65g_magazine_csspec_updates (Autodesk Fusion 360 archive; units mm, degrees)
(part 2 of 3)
sketch "follower top profile" plane through (0, 0, 0) normal (0, 1, 0) x axis (1, 0, 0)
  line L1 (10.49, 30.115) -> (10.49, 3.75)
  line L2 (7.3787, 34.5802) -> (7.3787, 52.364)
  line L3 (-7.3787, 34.7452) -> (-7.3787, 52.2758)
  line L4 (-10.49, 30.5753) -> (-10.49, 3.75)
  line L5 (-7.49, 0.75) -> (0, 0.75)
  line L6 (7.49, 0.75) -> (0, 0.75)
  line L7 (-6.25, 20.5961) -> (6.25, 20.5961)
  line L8 (0, 4.25) -> (0, 55.9239)
  line L9 (0, 0) -> (0, 4.25)
  line L10 (-6.25, 12.5809) -> (-6.25, 36.1163)
  line L11 (6.25, 36.1163) -> (6.25, 12.5809)
  line L12 (0, 12.5809) -> (0, 36.1163)
  line L13 (-6.25, 12.5809) -> (6.25, 12.5809)
  line L14 (6.2185, 35.49) -> (-6.2185, 35.49)
  line L15 (-6.25, 13.5809) -> (6.25, 13.5809)
  line L16 (6.25, 34.49) -> (-6.25, 34.49)
  line L17 (-4.25, 12.5809) -> (-4.25, 36.1163)
  line L18 (4.25, 36.1163) -> (4.25, 12.5809)
  line L19 (-7.49, 2.55) -> (0, 2.55)
  line L20 (-8.69, 29.5833) -> (-8.69, 3.75)
  line L21 (-5.5787, 33.643) -> (-5.5787, 52.212)
  line L22 (-3.8484, 54.1526) -> (0, 54.147)
  line L23 (3.9642, 54.1413) -> (0, 54.147)
  line L24 (5.5787, 33.643) -> (5.5787, 52.2656)
  line L25 (8.69, 29.2715) -> (8.69, 3.75)
  line L26 (7.49, 2.55) -> (0, 2.55)
  line L27 (-8.69, 8.75) -> (-10.49, 8.75)
  line L28 (10.49, 8.75) -> (8.69, 8.75)
  line L29 (-7.3787, 46.15) -> (-5.5787, 46.15)
  line L30 (7.3787, 46.15) -> (5.5787, 46.15)
  line L31 (11, 0) -> (0, 0)
  line L32 (-11, 0) -> (0, 0)
  line L33 (-1.5, 26.4663) -> (1.5, 26.4663)
  line L34 (-1.5, 20.5863) -> (-1.5, 26.4663)
  line L35 (1.5, 20.5863) -> (-1.5, 20.5863)
  line L36 (1.5, 26.4663) -> (1.5, 20.5863)
  line L37 (0, 20.5863) -> (0, 26.4663)
  line L38 (-1.5, 23.9663) -> (1.5, 23.9663)
  line L39 (-1.5, 18.0863) -> (-1.5, 20.5863)
  line L40 (1.5, 18.0863) -> (-1.5, 18.0863)
  line L41 (1.5, 20.5863) -> (1.5, 18.0863)
  line L42 (-2.4679, 4.7609) -> (1.7552, 4.7609)
  line L43 (0, 1.2302) -> (0, 0)
  line L44 (-8.69, 6.25) -> (8.69, 6.25)
  line L45 (-1.85, 3.3229) -> (1.85, 3.3229)
  line L46 (-1.85, 4.9829) -> (-1.85, 3.3229)
  line L47 (-0.6223, 4.8) -> (-0.6223, 4.6416)
  line L48 (1.85, 4.9829) -> (1.85, 3.3229)
  line L49 (5.5787, 48.15) -> (-5.5787, 48.15)
  line L50 (-3.9765, 37.6163) -> (3.9765, 37.6163)
  line L51 (7.3787, 33.643) -> (-7.3787, 33.643)
  line L52 (3.7962, 55.9465) -> (-3.9836, 55.9465)
  line L53 (9.7698, 31.6519) -> (8.0989, 33.0433)
  line L54 (-9.5582, 32.2662) -> (-8.3105, 33.0543)
  line L55 (-7.7582, 31.2742) -> (-6.5105, 32.0624)
  line L56 (7.9698, 30.8084) -> (6.2989, 32.1998)
  line L57 (5.5787, 33.7367) -> (5.5787, 33.643)
  line L58 (-5.5787, 33.7532) -> (-5.5787, 33.643)
  arc A1 centre (3.7962, 52.364) radius 3.5825 clockwise from (3.7962, 55.9465) to (7.3787, 52.364)
  arc A2 centre (-3.6968, 52.2758) radius 3.6819 clockwise from (-7.3787, 52.2758) to (-3.9836, 55.9465)
  arc A3 centre (7.49, 3.75) radius 3 clockwise from (10.49, 3.75) to (7.49, 0.75)
  arc A4 centre (-7.49, 3.75) radius 3 clockwise from (-7.49, 0.75) to (-10.49, 3.75)
  arc A5 centre (0, 12.5809) radius 6.25 clockwise from (6.25, 12.5809) to (-6.25, 12.5809)
  arc A6 centre (0, 36.1163) radius 6.25 clockwise from (-6.25, 36.1163) to (6.25, 36.1163)
  arc A7 centre (0, 36.1163) radius 4.25 clockwise from (-4.25, 36.1163) to (4.25, 36.1163)
  arc A8 centre (0, 12.5809) radius 4.25 clockwise from (4.25, 12.5809) to (-4.25, 12.5809)
  arc A9 centre (-7.49, 3.75) radius 1.2 clockwise from (-7.49, 2.55) to (-8.69, 3.75)
  arc A10 centre (-3.6968, 52.2758) radius 1.883 clockwise from (-5.5787, 52.212) to (-3.8484, 54.1526)
  arc A11 centre (3.7962, 52.364) radius 1.7852 clockwise from (3.9642, 54.1413) to (5.5787, 52.2656)
  arc A12 centre (7.49, 3.75) radius 1.2 clockwise from (8.69, 3.75) to (7.49, 2.55)
  arc A13 centre (0, 12.5809) radius 7.82 clockwise from (4.5904, 6.25) to (1.85, 4.9829)
  arc A14 centre (0, 12.5809) radius 7.82 clockwise from (-1.85, 4.9829) to (-4.5904, 6.25)
  arc A15 centre (-6.69, 29.5833) radius 2 clockwise from (-8.69, 29.5833) to (-7.7582, 31.2742)
  arc A16 centre (-8.49, 30.5753) radius 2 clockwise from (-10.49, 30.5753) to (-9.5582, 32.2662)
  arc A17 centre (-7.5787, 33.7532) radius 2 clockwise from (-5.5787, 33.7532) to (-6.5105, 32.0624)
  arc A18 centre (-9.3787, 34.7452) radius 2 clockwise from (-7.3787, 34.7452) to (-8.3105, 33.0543)
  arc A19 centre (6.69, 29.2715) radius 2 clockwise from (7.9698, 30.8084) to (8.69, 29.2715)
  arc A20 centre (7.5787, 33.7367) radius 2 clockwise from (6.2989, 32.1998) to (5.5787, 33.7367)
  arc A21 centre (8.49, 30.115) radius 2 clockwise from (9.7698, 31.6519) to (10.49, 30.115)
  arc A22 centre (9.3787, 34.5802) radius 2 clockwise from (8.0989, 33.0433) to (7.3787, 34.5802)
  point P29 (0, 12.5809)
  point P30 (-6.2185, 35.49)
  point P31 (6.2185, 35.49)
  point P34 (-6.25, 34.49)
  point P35 (6.25, 34.49)
  point P58 (-10.49, 8.75)
  point P59 (-8.69, 8.75)
  point P60 (8.69, 8.75)
  point P61 (10.49, 8.75)
  point P62 (-5.5787, 46.15)
  point P63 (-7.3787, 46.15)
  point P64 (5.5787, 46.15)
  point P65 (7.3787, 46.15)
  point P74 (0, 26.4663)
  point P75 (0, 20.5863)
  point P76 (1.5, 23.9663)
  point P77 (-1.5, 23.9663)
  point P68 (0, 0)
  point P83 (0, 0)
  point P85 (8.69, 6.25)
  point P86 (-8.69, 6.25)
  point P87 (-4.5904, 6.25)
  point P88 (4.5904, 6.25)
  point P94 (1.85, 4.9829)
  point P96 (-5.5787, 48.15)
  point P97 (5.5787, 48.15)
  point P98 (3.9765, 37.6163)
  point P99 (-3.9765, 37.6163)
  point P54 (5.5787, 33.643)
  point P46 (-5.5787, 33.643)
  point P10 (-7.3787, 33.643)
  point P2 (10.49, 31.0522)
  point P3 (7.3787, 33.643)
  point P18 (6.25, 20.5961)
  point P19 (-6.25, 20.5961)
  point P22 (0, 0)
  point P72 (-1.5, 20.5863)
  point P73 (1.5, 20.5863)
  point P78 (-1.5, 18.0863)
  point P89 (1.85, 3.3229)
  point P90 (-1.85, 3.3229)
  point P91 (-1.85, 4.9829)
  point P28 (0, 36.1163)
  point P36 (0, 36.1163)
  point P71 (-1.5, 26.4663)
  point P84 (0, 1.2302)
  tangent A2 L3
  tangent L2 A1
  tangent L1 A3
  tangent L6 A3
  tangent L4 A4
  tangent L5 A4
  equal A3 A4
  vertical L8
  tangent L10 A5
  tangent A5 L11
  parallel L10 L11
  tangent L11 A6
  tangent L10 A6
  coincident L8 P29
  parallel L8 L12
  coincident A6 P30
  coincident A6 P31
  perpendicular L10 L14
  coincident L10 P34
  coincident L11 P35
  coincident L4 P58
  coincident L20 P59
  perpendicular L20 L27
  coincident L25 P60
  coincident L1 P61
  perpendicular L1 L28
  coincident L21 P62
  coincident L3 P63
  perpendicular L3 L29
  coincident L24 P64
  coincident L2 P65
  perpendicular L2 L30
  horizontal L33
  vertical L34
  horizontal L35
  vertical L36
  midpoint L33 P74
  midpoint L35 P75
  collinear L12 L37
  coincident L36 P76
  coincident L34 P77
  perpendicular L34 L38
  horizontal L6
  horizontal L5
  perpendicular L35 L39
  vertical L41
  horizontal L40
  horizontal L42
  tangent L42 A14
  coincident P68 P83
  perpendicular L32 L43
  collinear L9 L43
  coincident L25 P85
  coincident L20 P86
  perpendicular L20 L44
  concentric A5 A14
  coincident L44 P87
  coincident L44 P88
  horizontal L45
  perpendicular L42 L46
  perpendicular L42 L47
  coincident P94 A14
  perpendicular L45 L48
  concentric A13 A14
  coincident L21 P96
  coincident L24 P97
  perpendicular L24 L49
  coincident A7 P98
  coincident A7 P99
  horizontal L50
  perpendicular L2 L51
  coincident P54 L51
  coincident P46 L51
  vertical L2
  tangent A1 L52
  concentric A4 A9
  concentric A2 A10
  concentric A1 A11
  concentric A3 A12
  tangent A12 L26
  tangent L25 A12
  tangent L19 A9
  tangent A9 L20
  perpendicular L51 L57
  perpendicular L51 L58
  tangent L20 A15
  tangent L55 A15
  tangent L4 A16
  tangent L54 A16
  equal A15 A16
  tangent L55 A17
  tangent L58 A17
  equal A15 A17
  coincident P10 L3
  coincident P10 L54
  tangent L3 A18
  tangent L54 A18
  tangent L25 A19
  tangent L56 A19
  tangent L56 A20
  tangent L57 A20
  equal A19 A20
  coincident P2 L1
  coincident P2 L53
  tangent L1 A21
  tangent L53 A21
  equal A19 A21
  coincident P3 L53
  coincident P3 L2
  tangent L53 A22
  tangent L2 A22
  dimension "d895" radius A3 = 3
  dimension "d938" distance P18 P19 = 12.5
  dimension "d943" distance P19 L8 = 6.25 (= "d938 / 2")
  dimension "d947" radius A5 = 6.25 (= "d938 / 2")
  dimension "d958" = 1
  dimension "d959" = 1
  dimension "d960" = -2
  dimension "d967" distance L5 L27 = 8
  dimension "d968" distance L6 L28 = 8 (= "d967")
  dimension "d1005" distance L5 P29 = 11.8309
  dimension "d1006" distance P22 P29 = 12.5809
  dimension "d1008" distance P72 P73 = 3
  dimension "d1010" distance L33 L38 = 2.5
  dimension "d1011" distance L5 L32 = 0.75
  dimension "d1012" distance P72 P78 = 2.5
  dimension "d1016" distance L35 L38 = 3.38
  dimension "d1018" distance L6 L44 = 5.5
  dimension "d1019" distance P89 P90 = 3.7
  dimension "d1020" distance L9 P90 = 1.85 (= "d1019 / 2")
  dimension "d1021" distance P90 P91 = 1.66
  dimension "d1022" distance L29 L49 = 2
  dimension "d1034" distance P28 L50 = 1.5
  dimension "d1099" distance P36 P71 = 9.65
  dimension "d1157" distance P2 L6 = 30.3022
  dimension "d1158" distance P3 L6 = 32.893
  dimension "d1159" distance L1 P84 = 10.49
  dimension "d1160" distance L4 L8 = 10.49 (= "d1159")
  dimension "d1161" distance L2 L3 = 14.7574
  dimension "d1162" distance L3 L8 = 7.3787 (= "d1161 / 2")
  dimension "d1165" radius A15 = 2
  dimension "d1166" radius A18 = 2
  dimension "d1167" radius A19 = 2
  dimension "d1168" radius A22 = 2
  dimension "d1169" distance L5 L52 = 55.1965
fillet "Fillet14" radius 1
sweep "Sweep2" sketch "follower top profile" TwistAngle 0 TaperAngle 0
extrude "Extrude1" new body sketch "follower top profile" profile of L6 A2 L5 L4 A1 L2 L3 L1 A3 A4 L7 L10 A5 L11 A6 L15 L16 L18 A8 L17 A7 L26 A12 L25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 against normal blind 4 bodies "definesSketchPlane"
sketch "bullet offsetter bump" plane through (0, 0, -0.75) normal (0, 0, 1) x axis (1, 0, 0)
  line L1 (-7.49, 0) -> (7.49, 0)
  line L2 (-7.49, -4) -> (-7.49, 0)
  line L3 (7.49, -4) -> (-7.49, -4)
  line L4 (7.49, 0) -> (7.49, -4)
  line L5 (-10.49, 0) -> (-7.49, 0)
  line L6 (-10.49, -4) -> (-10.49, 0)
  line L7 (-7.49, -4) -> (-10.49, -4)
  line L8 (-7.49, 0) -> (-7.49, -4)
  line L9 (-0.14, 0) -> (-10.49, 0)
  line L10 (-0.14, 4.5) -> (-0.14, 0)
  line L11 (-6.99, 4.5) -> (-0.14, 4.5)
  line L12 (-10.49, 0) -> (-10.49, 1)
  line L13 (-10.49, 1) -> (-6.99, 4.5)
  point P7 (-10.49, 0)
  point P10 (-10.49, 0)
  point P13 (-10.49, 0)
  point P12 (-10.49, 4.5)
  point P14 (-0.14, 4.5)
  point P15 (-0.14, 4.5)
  point P11 (-0.14, 0)
  point P16 (-6.99, 4.5)
  point P17 (-10.49, 1)
  coincident P7 P10
  perpendicular L6 L9
  perpendicular L1 L10
  coincident P7 P13
  horizontal L11
  vertical L12
  coincident P12 L11
  coincident P12 L12
  coincident P14 P15
  dimension "d900" distance P10 P11 = 10.35
  dimension "d903" distance P12 P16 = 3.5
  dimension "d904" distance P12 P17 = 3.5 (= "d903")
  dimension "d915" distance P11 P14 = 4.5
extrude "Extrude2" new body sketch "bullet offsetter bump" profile of L1 L5 L9 L10 L11 L12 L13 against normal blind 33.5
fillet "Fillet1" radius 3 2
fillet "Fillet6" radius 4
chamfer "Chamfer2" distance 4 distance 4
fillet "Fillet7" radius 2
extrude "Extrude4" new body sketch "follower top profile" profile of L10 L11 A6 L16 L18 L17 A7 L50 blind -7 from offset -2
work_plane "WorkPlane2" AlongDistance -12.79
sweep "Sweep1" sketch "follower top profile" TwistAngle 0 TaperAngle 0
sweep "Sweep3" sketch "follower top profile" TwistAngle 0 TaperAngle 0
sketch "Sketch3" plane through (0, -13.1437, -0.1123) normal (0, -1, -0.0085) x axis (-1, 0, 0)
  line L1 (7.3787, 52.2196) -> (7.3787, 46.0938)
  line L2 (-3.7962, 55.8903) -> (3.9836, 55.8903)
  line L3 (-7.3787, 46.0938) -> (-7.3787, 52.3078)
  line L4 (-5.5787, 46.0938) -> (-7.3787, 46.0938)
  line L5 (-5.5787, 48.0938) -> (-5.5787, 46.0938)
  line L6 (5.5787, 48.0938) -> (-5.5787, 48.0938)
  line L7 (5.5787, 46.0938) -> (5.5787, 48.0938)
  line L8 (7.3787, 46.0938) -> (5.5787, 46.0938)
  line L9 (-7.3787, 52.3078) -> (7.3787, 52.2196)
  line L10 (0.0937, 55.8903) -> (0, 52.2637)
  curve K1 (3.9836, 55.8903) -> (8.8529, 52.246)
  curve K2 (8.8529, 52.883) -> (8.8529, 51.6091)
  curve K3 (3.319, 55.8903) -> (4.6482, 55.8903)
  curve K4 (-4.5158, 55.8903) -> (-8.8608, 52.246)
  curve K5 (-8.8533, 52.8586) -> (-8.8639, 51.5848)
  curve K6 (-3.8512, 55.8848) -> (-5.1803, 55.8959)
  line L11 (3.9836, 55.8903) -> (-4.5158, 55.8903)
  line L12 (-8.8608, 52.246) -> (8.8529, 52.246)
  line L13 (6.6433, 50.0461) -> (-6.6586, 50.1035)
  arc A1 centre (3.6968, 52.2196) radius 3.6819 clockwise from (3.9836, 55.8903) to (7.3787, 52.2196)
  arc A2 centre (-3.7962, 52.3078) radius 3.5825 clockwise from (-7.3787, 52.3078) to (-3.7962, 55.8903)
  circle C1 centre (6.6529, 52.246) radius 2.2
  circle C2 centre (-6.6616, 52.3035) radius 2.2
  point P3 (7.3787, 52.2196)
  point P14 (7.3787, 52.2196)
  point P7 (-7.3787, 52.3078)
  point P15 (-7.3787, 52.3078)
  point P17 (0, 52.2637)
  point P18 (0.0937, 55.8903)
  point P4 (3.9836, 55.8903)
  point P19 (3.9836, 55.8903)
  point P16 (8.8529, 52.246)
  point P32 (6.6529, 52.246)
  point P33 (-6.6616, 52.3035)
  point P24 (-8.8608, 52.246)
  point P30 (-6.6586, 50.1035)
  point P31 (6.6433, 50.0461)
  coincident P3 P14
  coincident P7 P15
  midpoint L9 P17
  midpoint L2 P18
  coincident P4 P19
  midpoint P16 K2
  vertical K2
  midpoint P19 K3
  horizontal K3
  parallel K3 L11
  horizontal L12
  coincident L12 P32
  coincident L9 P33
  coincident P24 C2
  coincident P16 C1
  coincident P30 C2
  coincident P31 C1
  tangent L13 C1
  dimension "d1174" diameter C1 = 4.4 (= "( 2.2 * 2 ) * 1 mm")
  dimension "d1175" diameter C2 = 4.4
extrude "Extrude10" add sketch "Sketch3" profile of L1 A1 L2 A2 L3 L4 L5 L6 L7 L8 L9 K1 K4 L11 L12 L13 C1 C2 along normal blind 6
chamfer "Chamfer9" distance 0.7 distance 27
extrude "Extrude8" add sketch "follower top profile" profile of L13 L33 L34 L35 L36 L38 L39 L40 L41 against normal blind 5.5
extrude "Extrude9" add sketch "follower top profile" profile of L7 L33 L34 L35 L36 L38 L39 L40 L41 blind -2 from offset -5.5
fillet "Fillet9" radius 1.5
fillet "Fillet10" radius 1.5
combine "Combine2"
chamfer "Chamfer7" distance 0.5 distance 1
fillet "Fillet11" radius 1
chamfer "Chamfer8" distance 0.5 distance 12
fillet "Fillet12" radius 2
move "Move2"
extrude "Extrude6" add sketch "new profile" profile of L16 L17 L18 L19 along normal blind 7
fillet "Fillet1" radius 1.524 0.762
fillet "Fillet6" radius 2.54
chamfer "Chamfer2" distance 0.4826
chamfer "Chamfer3" distance 2.0574
fillet "Fillet7" radius 2.54
sketch "springRetentionNew" plane through (0, 0, 0) normal (0, 1, 0) x axis (1, 0, 0)
  line L1 (4.25, 36.1163) -> (4.25, 12.5809)
  line L2 (6.25, 36.1163) -> (6.25, 12.5809)
  line L3 (-4.25, 12.5809) -> (-4.25, 36.1163)
  line L4 (-6.25, 12.5809) -> (-6.25, 36.1163)
  line L5 (7.75, 14.9309) -> (6.25, 14.9309)
  line L6 (7.75, 21.9309) -> (7.75, 14.9309)
  line L7 (6.25, 21.9309) -> (7.75, 21.9309)
  line L8 (6.25, 14.9309) -> (6.25, 21.9309)
  line L9 (0, 36.1163) -> (0, 12.5809)
  line L10 (0, 4.25) -> (0, 55.9239)
  line L11 (-6.25, 14.9309) -> (-6.25, 21.9309)
  line L12 (-7.75, 14.9309) -> (-6.25, 14.9309)
  line L13 (-6.25, 21.9309) -> (-7.75, 21.9309)
  line L14 (-7.75, 21.9309) -> (-7.75, 14.9309)
  line L15 (2.2447, 6.3309) -> (-1.7458, 6.3309)
  line L16 (8.75, 13.9309) -> (5.25, 13.9309)
  line L17 (8.75, 22.9309) -> (8.75, 13.9309)
  line L18 (5.25, 22.9309) -> (8.75, 22.9309)
  line L19 (5.25, 13.9309) -> (5.25, 22.9309)
  line L20 (-5.25, 22.9309) -> (-8.75, 22.9309)
  line L21 (-5.25, 13.9309) -> (-5.25, 22.9309)
  line L22 (-8.75, 13.9309) -> (-5.25, 13.9309)
  line L23 (-8.75, 22.9309) -> (-8.75, 13.9309)
  arc A1 centre (0, 12.5809) radius 6.25 clockwise from (6.25, 12.5809) to (-6.25, 12.5809)
  arc A2 centre (0, 36.1163) radius 6.25 clockwise from (-6.25, 36.1163) to (6.25, 36.1163)
  arc A3 centre (0, 36.1163) radius 4.25 clockwise from (-4.25, 36.1163) to (4.25, 36.1163)
  arc A4 centre (0, 12.5809) radius 4.25 clockwise from (4.25, 12.5809) to (-4.25, 12.5809)
  point P18 (6.25, 14.9309)
  point P4 (0, 12.5809)
  point P22 (0, 12.5809)
  point P10 (0, 36.1163)
  point P23 (0, 36.1163)
  point P27 (-6.25, 14.9309)
  point P19 (7.75, 14.9309)
  point P28 (-7.75, 14.9309)
  point P20 (7.75, 21.9309)
  point P29 (-7.75, 21.9309)
  point P21 (6.25, 21.9309)
  point P26 (-6.25, 21.9309)
  horizontal L5
  vertical L6
  horizontal L7
  vertical L8
  coincident L2 P18
  coincident P4 P22
  coincident P10 P23
  symmetric P18 L10 P27
  symmetric P19 L10 P28
  symmetric P20 L10 P29
  symmetric P21 L10 P26
  perpendicular L10 L15
  tangent A1 L15
  dimension "d1054" distance P18 P19 = 1.5
  dimension "d1055" distance P18 P21 = 7
  dimension "d1056" distance L5 L15 = 8.6
  dimension "d1065" = 1
  dimension "d1066" = -1
extrude "Extrude7" add sketch "springRetentionNew" profile of A1 A2 A3 L1 L2 A4 L3 L4 L8 L11 L19 L18 L16 L22 L21 L20 against normal blind 4
extrude "Extrude8" add sketch "springRetentionNew" profile of L2 L4 L5 L6 L7 L8 L11 L12 L13 L14 to an object from offset -1.8034
draft "Draft1" Angle1 55 Angle2 0
draft "Draft2" Angle1 55 Angle2 0
chamfer "Chamfer1" distance 0.5
extrude "Extrude9" cut sketch "springRetentionNew" profile of L2 L4 L5 L6 L7 L8 L11 L12 L13 L14 L18 L17 L16 L22 L23 L20 along normal blind 4
fillet "Fillet2" radius 1
sketch "addtlReinforcement" plane through (0, -4, 0) normal (0, -1, 0) x axis (1, 0, 0)
  line L1 (7.75, -15.2462) -> (7.75, -21.6156)
  line L2 (6.43, -13.0458) -> (7.5692, -14.6727)
  line L3 (-7.5692, -14.6727) -> (-6.43, -13.0458)
  line L4 (-7.75, -21.6156) -> (-7.75, -15.2462)
  line L5 (-6.4308, -23.8149) -> (-7.5692, -22.1892)
  line L6 (-6.25, -36.1163) -> (-6.25, -24.3885)
  line L7 (6.25, -24.3885) -> (6.25, -36.1163)
  line L8 (7.5692, -22.1892) -> (6.4308, -23.8149)
  line L9 (-6.2963, -24.0877) -> (6.2963, -24.0877)
  line L10 (6.2977, -12.7801) -> (-6.2977, -12.7801)
  line L11 (7.75, -17.0877) -> (-7.75, -17.0877)
  line L12 (-7.75, -20.0877) -> (7.75, -20.0877)
  arc A1 centre (6.75, -21.6156) radius 1 clockwise from (7.75, -21.6156) to (7.5692, -22.1892)
  arc A2 centre (6.75, -15.2462) radius 1 clockwise from (7.5692, -14.6727) to (7.75, -15.2462)
  arc A3 centre (7.2492, -12.4723) radius 1 clockwise from (6.43, -13.0458) to (6.2493, -12.4872)
  arc A4 centre (0, -12.5809) radius 6.25 clockwise from (-6.2493, -12.4872) to (6.2493, -12.4872)
  arc A5 centre (-7.2492, -12.4723) radius 1 clockwise from (-6.2493, -12.4872) to (-6.43, -13.0458)
  arc A6 centre (-6.75, -15.2462) radius 1 clockwise from (-7.75, -15.2462) to (-7.5692, -14.6727)
  arc A7 centre (-6.75, -21.6156) radius 1 clockwise from (-7.5692, -22.1892) to (-7.75, -21.6156)
  arc A8 centre (-7.25, -24.3885) radius 1 clockwise from (-6.4308, -23.8149) to (-6.25, -24.3885)
  arc A9 centre (0, -36.1163) radius 6.25 clockwise from (6.25, -36.1163) to (-6.25, -36.1163)
  arc A10 centre (7.25, -24.3885) radius 1 clockwise from (6.25, -24.3885) to (6.4308, -23.8149)
  point P30 (6.2963, -24.0877)
  point P31 (-6.2963, -24.0877)
  point P32 (-6.2977, -12.7801)
  point P33 (6.2977, -12.7801)
  point P34 (-7.75, -17.0877)
  point P35 (7.75, -17.0877)
  point P36 (7.75, -20.0877)
  point P37 (-7.75, -20.0877)
  midpoint A10 P30
  midpoint A8 P31
  midpoint A5 P32
  midpoint A3 P33
  coincident L4 P34
  coincident L1 P35
  perpendicular L1 L11
  coincident L1 P36
  coincident L4 P37
  perpendicular L4 L12
  dimension "d1071" distance L11 L12 = 3
  dimension "d1072" distance L9 L12 = 4
extrude "Extrude10" add sketch "addtlReinforcement" profile of L1 L4 L11 L12 along normal blind 1 taper -30
fillet "Fillet3" radius 2 1
fillet "Fillet4" radius 0.25
fillet "Fillet5" radius 0.508 1.905
sketch "Sketch1" plane through (0, 0, 0) normal (1, 0, 0) x axis (0, 1, 0)
  line L1 (5.675, 0) -> (0, 0)
  line L2 (5.9411, 0.38) -> (5.675, 0)
  line L3 (5.9411, 1.45) -> (5.9411, 0.38)
  line L4 (4.775, 1.45) -> (5.9411, 1.45)
  line L5 (4.775, 2.64) -> (4.775, 1.45)
  line L6 (5.626, 3.1808) -> (4.775, 2.64)
  line L7 (5.0285, 30.441) -> (5.626, 3.1808)
  line L8 (4.305, 32.735) -> (5.0285, 30.441)
  line L9 (4.28, 38.81) -> (4.305, 32.735)
  line L10 (0, 38.7924) -> (4.28, 38.81)
  line L11 (0, 0) -> (0, 38.7924)
  line L12 (3.95, 38.7924) -> (0, 38.7924)
  line L13 (0, 55.88) -> (0, 38.7924)
  line L14 (0, 0) -> (0, 55.88)
  curve K1 (0, 55.88) -> (3.95, 38.7924)
  curve K2 (-0.929, 55.88) -> (0.929, 55.88)
  curve K3 (3.95, 40.5596) -> (3.95, 37.0251)
  point P1 (0, 0)
  point P2 (0, 0)
  point P15 (0, 0)
  point P14 (0, 55.88)
  point P13 (3.95, 38.7924)
  point P3 (5.675, 0)
  point P6 (4.775, 1.45)
  point P7 (4.775, 2.64)
  point P4 (5.9411, 0.38)
  point P5 (5.9411, 1.45)
  point P8 (5.626, 3.1808)
  point P9 (5.0285, 30.441)
  point P10 (4.305, 32.735)
  point P11 (4.28, 38.81)
  point P12 (0, 38.7924)
  coincident P1 P2
  horizontal L1
  perpendicular L1 L3
  perpendicular L3 L4
  perpendicular L4 L5
  perpendicular L9 L10
  vertical L11
  perpendicular L11 L12
  perpendicular L12 L13
  coincident P1 P15
  midpoint P14 K2
  horizontal K2
  midpoint P13 K3
  vertical K3
  dimension "d1114" distance P2 P3 = 5.675 (= "( 11.35 / 2 ) * 1 mm")
  dimension "d1115" distance L5 L11 = 4.775 (= "( 9.55 / 2 ) * 1 mm")
  dimension "d1116" distance P6 P7 = 1.19
  dimension "d1117" distance L1 L4 = 1.45
  dimension "d1120" angle L1 L2 = 125 (= "90 deg + 35 deg")
  dimension "d1121" distance P4 P5 = 1.07
  dimension "d1122" distance P8 L11 = 5.626 (= "( 11.252 / 2 ) * 1 mm")
  dimension "d1123" distance P9 L11 = 5.0285 (= "( 10.057 / 2 ) * 1 mm")
  dimension "d1124" distance L1 P9 = 30.441
  dimension "d1125" distance L1 P10 = 32.735
  dimension "d1126" distance P10 L11 = 4.305 (= "( 8.61 / 2 ) * 1 mm")
  dimension "d1127" distance P11 L11 = 4.28 (= "( 8.56 / 2 ) * 1 mm")
  dimension "d1129" distance L1 P11 = 38.81
  dimension "d1130" distance P12 P13 = 3.95
  dimension "d1131" distance P1 P14 = 55.88
  dimension "d1136" angle L7 L11 = 1.256
revolve "Revolve1" sketch "Sketch1" AlongAngle 360
sketch "Sketch2" plane through (0, 0, 0) normal (0, 0, -1) x axis (-1, 0, 0)
  line L1 (84.8237, -5.675) -> (-1.9926, -5.675)
  line L2 (-1.9926, 16.325) -> (-1.9926, -5.675)
  line L3 (84.8237, 16.325) -> (-1.9926, 16.325)
  line L4 (84.8237, 16.325) -> (84.8237, -5.675)
  circle C1 centre (0, 0) radius 5.675
  circle C2 centre (0, 0) radius 2.1971
  point P1 (0, 0)
  point P3 (0, 0)
  point P4 (-1.9926, -5.675)
  point P6 (-1.9926, 16.325)
  coincident P1 P3
  horizontal L1
  tangent C1 L1
  perpendicular L1 L2
  perpendicular L2 L3
  dimension "d1133" diameter C2 = 4.3942
  dimension "d1138" distance P4 P6 = 22
extrude "Extrude1" cut sketch "Sketch2" profile of C2 against normal blind 3.1242
copy_paste_bodies "CopyPasteBodies2"
move "Move2"
copy_paste_bodies "CopyPasteBodies3"
move "Move3"
move "Move4"
copy_paste_bodies "CopyPasteBodies4"
move "Move5"
copy_paste_bodies "CopyPasteBodies5"
move "Move6"
copy_paste_bodies "CopyPasteBodies6"
move "Move7"
copy_paste_bodies "CopyPasteBodies7"
move "Move8"
copy_paste_bodies "CopyPasteBodies8"
move "Move9"
copy_paste_bodies "CopyPasteBodies9"
move "Move10"
copy_paste_bodies "CopyPasteBodies10"
move "Move11"
move "Move12"
move "Move13"
move "Move14"
move "Move15"
move "Move16"
move "Move17"
move "Move18"
move "Move19"
extrude "Extrude1" new body sketch "Sketch2" against normal blind 60
draft "Draft1" Angle1 -1.25 Angle2 0
shell "Shell1" outerThickness 2
sketch "Sketch1" plane through (0, 18.3168, 0.3997) normal (0, 0.9998, 0.0218) x axis (1, 0, 0)
  line L1 (-86.8237, 2.4002) -> (3.9926, 2.4002)
  line L2 (-86.8237, -61.615) -> (-86.8237, 2.4002)
  line L3 (3.9926, -61.615) -> (-86.8237, -61.615)
  line L4 (3.9926, 2.4002) -> (3.9926, -61.615)
  line L5 (-5.0074, -52.615) -> (-77.8237, -52.615)
  line L6 (-5.0074, -6.5998) -> (-5.0074, -52.615)
  line L7 (-77.8237, -6.5998) -> (-5.0074, -6.5998)
  line L8 (-77.8237, -52.615) -> (-77.8237, -6.5998)
  curve K1 (-46.7288, -36.635) -> (-43.8154, -53.9119)
  curve K2 (-43.8154, -53.9119) -> (-54.0221, -39.671)
  line L9 (-48.7358, -30.8899) -> (-46.4242, -36.508)
  line L10 (-56.6846, -34.1988) -> (-54.3268, -39.7977)
  line L11 (-48.9495, -28.494) -> (-48.7358, -30.8899)
  line L12 (-58.2341, -32.359) -> (-56.6846, -34.1988)
  line L13 (-58.8742, -3.0977) -> (-48.9495, -28.494)
  line L14 (-69.2621, -7.4219) -> (-58.2341, -32.359)
  line L15 (-69.2621, -7.4219) -> (-68.6843, -6.5956)
  line L16 (-58.8742, -3.0977) -> (-59.8677, -2.9255)
  line L17 (-60.3249, -1.8271) -> (-59.8677, -2.9255)
  line L18 (-69.1415, -5.4973) -> (-68.6843, -6.5956)
  line L19 (-59.6597, -0.3909) -> (-59.2485, -1.3787)
  line L20 (-70.6293, -4.9573) -> (-70.2181, -5.9451)
  line L21 (-70.6293, -4.9573) -> (-70.5297, -4.5042)
  line L22 (-59.6597, -0.3909) -> (-60.0513, -0.1423)
  closed curve K3 centre (-53.5918, -30.4265)
  closed curve K4 centre (-64.0681, -5.2598)
  closed curve K5 centre (-50.3755, -38.1528)
  closed curve K6 centre (-64.7333, -3.6619)
  closed curve K7 centre (-64.7333, -3.6619)
  closed curve K8 centre (-65.2905, -2.3233)
  dimension "d1148" = -9
  dimension "d1153" angle L8 L14 = 23.856
extrude "Extrude2" cut sketch "Sketch1" profile of L7 L8 L6 L5 against normal blind 65
extrude "Extrude3" cut of existing geometry blind -10
sketch "Sketch3" plane through (0, 0, -2) normal (0, 0, -1) x axis (-1, 0, 0)
  line L1 (86.8237, -7.7191) -> (-3.9926, -7.7191)
  line L2 (86.8237, 18.3691) -> (86.8237, -7.7191)
  line L3 (-3.9926, 18.3691) -> (86.8237, 18.3691)
  line L4 (-3.9926, -7.7191) -> (-3.9926, 18.3691)
  line L5 (84.8237, 16.325) -> (84.8237, -5.675)
  line L6 (84.8237, -5.675) -> (-1.9926, -5.675)
  line L7 (84.8237, 16.325) -> (-1.9926, 16.325)
  line L8 (79.3394, 16.325) -> (79.3394, -5.675)
  line L9 (68.6888, -5.675) -> (79.3394, -5.675)
  line L10 (74.8883, 8.8792) -> (68.6888, 1.5284)
  line L11 (74.8883, 16.325) -> (74.8883, 8.8792)
  line L12 (68.6888, 1.5284) -> (68.6888, -5.675)
  point P10 (79.3394, -5.675)
  point P11 (79.3394, 16.325)
  point P12 (68.6888, -5.675)
  point P15 (74.8883, 16.325)
  coincident L6 P10
  coincident L7 P11
  perpendicular L7 L8
  coincident L6 P12
  coincident L7 P15
  perpendicular L7 L11
  perpendicular L6 L12
extrude "Extrude3" new body sketch "Sketch3" profile of L6 L7 L8 L9 L10 L11 L12 blind -53 from offset -4
move "Move20"
remove_body "RemoveBody2"
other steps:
step "Fillet1" AlongDistance 3 TaperAngle 0 Radius 1 AlongDistance 2.5 TaperAngle 0
step "Fillet2" Radius 2
step "Fillet3" Radius 0.5
derived_base_feature "Derived Base Feature1" bodies "floor plate"
extrude "Extrude4" cut sketch "cut draft angle between feed lips" profile of L1 L2 L3 L4 L5 against normal blind 13.5
extrude "Extrude11" cut sketch "Rear locking lug profile" profile of L3 A1 L6 L7 L8 distance 5.8
create_component "CreateComponent2"
create_component "CreateComponent3"
create_component "CreateComponent4"
create_component "CreateComponent5"
base_feature "Base Feature2"
base_feature "Base Feature3"
base_feature "Base Feature4"
base_feature "Base Feature5"
base_feature "Base Feature6"
base_feature "Base Feature7"
base_feature "Base Feature8"
base_feature "Base Feature9"
base_feature "Base Feature10"
create_component "CreateComponent6"
named bodies: "follower", "mag body", "feed geometry", "random cube", "placeholder to establish center", "SUPPORT V1", "feed geometry (1)", "main body", "draft tool", "feed lip", "feed lip (1)", "floor plate", "floorPlate", "true rear lock lug", "MagpulFollower_223556", "MagpulFollower_223556 (1)", "MagpulFollower_223556 (2)", "MagpulFollower_223556 (3)", "MagpulFollower_223556 (4)", "definesSketchPlane", "Follower", "updated lock lug", "template lock lug from m76", "updated locking lug"

design "65_g_floorplate"
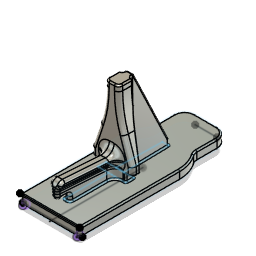
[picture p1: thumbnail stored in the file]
sketch "top profile" plane through (0, 0, 0) normal (0, 1, 0) x axis (1, 0, 0)
  line L1 (20.7, 0) -> (0, 0)
  line L2 (20.7, 38.9995) -> (20.7, 0)
  line L3 (18.085, 52.7) -> (18.085, 38.9995)
  line L4 (5.315, 55.4) -> (15.385, 55.4)
  line L5 (2.615, 39.6) -> (2.615, 52.7)
  line L6 (0, 39.6) -> (2.615, 39.6)
  line L7 (0, 0) -> (0, 39.6)
  line L8 (2.615, 39.6) -> (0, 39.6)
  line L9 (20.7, 38.9995) -> (18.085, 38.9995)
  curve K1 (20.7, 38.9995) -> (18.085, 44.77)
  curve K2 (19.0439, 42.5779) -> (18.3507, 43.501)
  line L10 (10.35, 55.4) -> (10.35, 0)
  curve K3 (0, 38.9995) -> (2.615, 44.77)
  curve K4 (18.1695, 43.9977) -> (18.0005, 45.5423)
  curve K5 (20.6925, 38.3395) -> (20.7075, 39.6594)
  curve K6 (2.5305, 43.9977) -> (2.6995, 45.5423)
  curve K7 (1.6561, 42.5779) -> (2.3493, 43.501)
  curve K8 (0.0075, 38.3395) -> (-0.0075, 39.6594)
  line L11 (0, 38.9995) -> (2.615, 38.9995)
  line L12 (2.615, 55.4) -> (2.615, 38.9995)
  line L13 (10.35, 0) -> (0, 0)
  line L14 (10.35, 36.4) -> (10.35, 0)
  line L15 (0, 36.4) -> (10.35, 36.4)
  line L16 (0, 0) -> (0, 36.4)
  line L17 (5.175, 28.09) -> (5.175, 36.4)
  line L18 (0, 29.925) -> (0, 36.4)
  line L19 (4.421, 36.4) -> (0, 36.4)
  line L20 (5.563, 36.4) -> (4.421, 36.4)
  line L21 (0, 992.6) -> (0, 0)
  line L22 (66.3724, 992.6) -> (0, 992.6)
  arc A1 centre (5.315, 52.7) radius 2.7 clockwise from (2.615, 52.7) to (5.315, 55.4)
  arc A2 centre (15.385, 52.7) radius 2.7 clockwise from (15.385, 55.4) to (18.085, 52.7)
  point P1 (0, 0)
  point P2 (0, 0)
  point P10 (18.085, 44.77)
  point P11 (18.6973, 43.0394)
  point P4 (20.7, 38.9995)
  point P20 (0, 38.9995)
  point P6 (18.085, 38.9995)
  point P31 (2.615, 38.9995)
  point P7 (18.085, 55.4)
  point P32 (2.615, 55.4)
  point P17 (2.615, 44.77)
  point P18 (2.0027, 43.0394)
  point P12 (20.041, 41.5358)
  point P19 (0.659, 41.5358)
  point P13 (18.3507, 43.501)
  point P27 (2.3493, 43.501)
  point P14 (19.0439, 42.5779)
  point P28 (1.6561, 42.5779)
  point P21 (18.0005, 45.5423)
  point P25 (2.6995, 45.5423)
  point P22 (18.1695, 43.9977)
  point P26 (2.5305, 43.9977)
  point P23 (20.7075, 39.6594)
  point P29 (-0.0075, 39.6594)
  point P24 (20.6925, 38.3395)
  point P30 (0.0075, 38.3395)
  point P16 (10.35, 55.4)
  point P8 (2.615, 55.4)
  point P15 (10.35, 0)
  point P3 (20.7, 0)
  point P43 (0, 0)
  point P46 (0, 36.4)
  point P47 (5.175, 36.4)
  point P41 (0, 0)
  point P42 (0, 0)
  point P40 (20.7, 0)
  point P52 (0, 0)
  point P44 (10.35, 0)
  point P45 (10.35, 36.4)
  point P48 (5.175, 28.09)
  point P49 (0, 29.925)
  point P50 (4.421, 36.4)
  point P51 (5.563, 36.4)
  point P53 (0, 992.6)
  coincident P1 P2
  horizontal L1
  perpendicular L1 L2
  perpendicular L3 L4
  perpendicular L1 L7
  perpendicular L5 L8
  perpendicular L2 L9
  coincident L3 P10
  midpoint P11 K2
  midpoint P10 K4
  midpoint P4 K5
  symmetric P4 L10 P20
  symmetric P6 L10 P31
  symmetric P7 L10 P32
  symmetric P10 L10 P17
  symmetric P11 L10 P18
  symmetric P12 L10 P19
  symmetric P13 L10 P27
  symmetric P14 L10 P28
  symmetric L10 P21 P25
  symmetric L10 P22 P26
  symmetric L10 P23 P29
  symmetric L10 P24 P30
  coincident L4 P16
  coincident P8 L4
  coincident P8 L5
  tangent L4 A1
  tangent L5 A1
  coincident P7 L3
  coincident P7 L4
  tangent L3 A2
  tangent L4 A2
  coincident L1 P15
  coincident P3 L1
  coincident P3 L2
  coincident P2 L1
  coincident P1 P43
  perpendicular L10 L13
  perpendicular L1 L14
  coincident L7 P46
  perpendicular L7 L15
  midpoint L15 P47
  perpendicular L15 L17
  perpendicular L15 L18
  perpendicular L7 L19
  perpendicular L17 L20
  coincident P1 P41
  parallel L1 L13
  coincident P2 P42
  coincident P3 P40
  coincident P2 P52
  perpendicular L13 L21
  perpendicular L21 L22
  dimension "d1" distance P2 P3 = 20.7
  dimension "d5" distance P7 P8 = 15.47
  dimension "d7" radius A1 = 2.7
  dimension "d8" radius A2 = 2.7
  dimension "d11" distance P43 P44 = 10.35
  dimension "d12" distance P44 P45 = 36.4
  dimension "d13" distance P47 P48 = 8.31
  dimension "d14" distance P46 P49 = 6.475
  dimension "d15" distance P46 P50 = 4.421
  dimension "d16" distance P50 P51 = 1.142
  dimension "d55" distance P52 P53 = 992.6
  dimension "d263" diameter = 11.2
  dimension "d264" diameter = 11.2
  dimension "d265" diameter = 11.2
  dimension "d266" distance = 5.6
  dimension "d267" distance = 9.5
  dimension "d268" distance = 4.5
  dimension "d269" distance = 5.6
  dimension "d270" distance = 0.5495
  dimension "d271" diameter = 11.2
  dimension "d272" diameter = 11.2
  dimension "d273" diameter = 11.2
  dimension "d274" diameter = 11.2
  dimension "d275" diameter = 11.2
  dimension "d276" distance = 22
  dimension "d277" diameter = 11.2
  dimension "d278" distance = 22
  dimension "d279" diameter = 11.2
  dimension "d280" diameter = 11.2
  dimension "d281" diameter = 11.2
  dimension "d282" distance = 9.5
  dimension "d283" distance = 4.5
  dimension "d284" diameter = 11.2
  dimension "d285" distance = 4.5
  dimension "d286" distance = 9.5
  dimension "d287" distance = 54.4
  dimension "d296" distance = 47
  dimension "d298" distance = 7
  dimension "d299" distance = 5
  dimension "d300" distance = 20
  dimension "d301" distance = 32
  dimension "d302" distance = 36
extrude "Extrude1" new body sketch "top profile" profile of L1 L7 L10 L13 L14 L15 L16 L18 L20 along normal blind 4.5
fillet "Fillet1" radius 3
sketch "uppermost feature" plane through (0, 4.5, 0) normal (0, 1, 0) x axis (-1, 0, 0)
  line L1 (0, -36.4) -> (-10.35, -36.4)
  line L2 (0, 0) -> (0, -36.4)
  line L3 (-10.35, 0) -> (0, 0)
  line L4 (-10.35, -36.4) -> (-10.35, 0)
split "Split1"
combine "Combine1"
chamfer "Chamfer2" distance 4 Rotate Angle 30
chamfer "Chamfer4" distance 3 Rotate Angle 60
draft "Draft2" Angle1 40 Angle2 0
chamfer "Chamfer5" distance 3 Rotate Angle 50
fillet "Fillet4" radius 3
fillet "Fillet5" radius 1.25
fillet "Fillet6" radius 9.5
fillet "Fillet7" radius 2
fillet "Fillet8" radius 1.5
fillet "Fillet9" radius 10.5
fillet "Fillet10" radius 1.5
revolve "Revolve1" sketch "top profile" AlongAngle -0.183
offset_faces "OffsetFaces1" distance 4
offset_faces "OffsetFaces2" distance 4
fillet "Fillet11" radius 11
fillet "Fillet12" radius 4.5
fillet "Fillet13" radius 2
fillet "Fillet14" radius 2
fillet "Fillet15" radius 0.75
sketch "bottom spring support" plane through (0, -3.1703, -0.0101) normal (0, -1, -0.0032) x axis (-1, 0, 0)
  line L1 (0, 35.8746) -> (0, 1.9949)
  line L2 (-2.615, 52.6949) -> (-2.615, 44.4901)
  line L3 (-15.385, 55.3949) -> (-5.315, 55.3949)
  line L4 (-18.085, 44.4901) -> (-18.085, 52.6949)
  line L5 (-20.7, 1.9949) -> (-20.7, 35.8746)
  line L6 (-2, -0.0051) -> (-18.7, -0.0051)
  line L7 (-20.7, 35.4949) -> (-20.7, -0.0051)
  line L8 (-19.062, 35.4949) -> (-20.7, 35.4949)
  line L9 (-24.0146, 1.1159) -> (-24.0146, -0.0051)
  line L10 (-19.062, 1.1159) -> (-19.062, 35.4949)
  line L11 (-10.35, 36.3998) -> (-10.35, 0)
  line L12 (-1.638, 35.4949) -> (0, 35.4949)
  line L13 (0, 0) -> (0, 35.4949)
  line L14 (-20.7, -0.0051) -> (0, 0)
  line L15 (-1.638, 1.1159) -> (-1.638, 35.4949)
  line L16 (-19.062, 1.1159) -> (-1.638, 1.1159)
  arc A1 centre (-2, 1.9949) radius 2 clockwise from (0, 1.9949) to (-2, -0.0051)
  arc A2 centre (-11, 35.8746) radius 11 clockwise from (-1.8558, 41.9888) to (0, 35.8746)
  arc A3 centre (-5.315, 52.6949) radius 2.7 clockwise from (-5.315, 55.3949) to (-2.615, 52.6949)
  arc A4 centre (-15.385, 52.6949) radius 2.7 clockwise from (-18.085, 52.6949) to (-15.385, 55.3949)
  arc A5 centre (-9.7, 35.8746) radius 11 clockwise from (-20.7, 35.8746) to (-18.8442, 41.9888)
  arc A6 centre (-18.7, 1.9949) radius 2 clockwise from (-18.7, -0.0051) to (-20.7, 1.9949)
  arc A7 centre (1.885, 44.4901) radius 4.5 clockwise from (-1.8558, 41.9888) to (-2.615, 44.4901)
  arc A8 centre (-22.585, 44.4901) radius 4.5 clockwise from (-18.085, 44.4901) to (-18.8442, 41.9888)
  point P23 (-20.7, 35.4949)
  point P30 (0, 35.4949)
  point P24 (-19.062, 35.4949)
  point P31 (-1.638, 35.4949)
  point P1 (0, 0)
  point P32 (0, 0)
  point P33 (0, 0)
  point P25 (-24.0146, -0.0051)
  point P26 (-24.0146, 1.1159)
  perpendicular L6 L7
  perpendicular L7 L8
  symmetric P23 L11 P30
  symmetric P24 L11 P31
  coincident P1 P32
  perpendicular L12 L13
  coincident P1 P33
  perpendicular L10 L16
  dimension "d70" distance P23 P24 = 1.638
  dimension "d71" distance P25 P26 = 1.121
revolve "Revolve2" sketch "bottom spring support" AlongAngle 2.7
fillet "Fillet18" radius 1.75
fillet "Fillet17" radius 0.75
sketch "cartrige ref dims" plane through (0, 0, 0) normal (0, 1, 0) x axis (1, 0, 0)
  line L1 (32, 0) -> (0, 0)
  line L2 (32, 32.242) -> (32, 0)
  line L3 (40.4093, 0) -> (32, 0)
  line L4 (40.4093, 29.227) -> (40.4093, 0)
  line L5 (51, 0) -> (40.4093, 0)
  line L6 (51, 54.32) -> (51, 0)
  line L7 (55.5931, 0) -> (51, 0)
  line L8 (55.5931, 57.4) -> (55.5931, 0)
  point P1 (0, 0)
  point P2 (0, 0)
  point P3 (32, 0)
  point P4 (32, 32.242)
  point P5 (40.4093, 0)
  point P6 (40.4093, 29.227)
  point P7 (51, 0)
  point P8 (51, 54.32)
  point P9 (55.5931, 0)
  point P10 (55.5931, 57.4)
  coincident P1 P2
  horizontal L1
  perpendicular L1 L2
  perpendicular L2 L3
  perpendicular L3 L4
  perpendicular L4 L5
  perpendicular L5 L6
  perpendicular L6 L7
  perpendicular L7 L8
  dimension "d79" distance P3 P4 = 32.242
  dimension "d80" distance P5 P6 = 29.227
  dimension "d81" distance P7 P8 = 54.32
  dimension "d82" distance P9 P10 = 57.4
sketch "mag body proper" plane through (0, 0, 0) normal (0, 1, 0) x axis (1, 0, 0)
  line L1 (2.615, 52.7048) -> (2.615, 44.5)
  line L2 (15.385, 55.4048) -> (5.315, 55.4048)
  line L3 (18.085, 44.5) -> (18.085, 52.7048)
  curve K1 (0.0859, 37.2565) -> (0.0311, 36.7114)
  line L4 (0.0311, 36.7114) -> (0, 36.7114)
  curve K2 (20.6689, 36.7114) -> (20.6141, 37.2565)
  line L5 (20.7, 36.7114) -> (20.6689, 36.7114)
  line L6 (20.7, 3.2538) -> (20.7, 36.7114)
  line L7 (20.7, 2.0003) -> (20.7, 3.2538)
  curve K3 (8.3837, 0.0003) -> (8.35, 0)
  line L8 (15.385, 55.4048) -> (5.315, 55.4048)
  line L9 (10.35, 56.4025) -> (10.35, -0.9975)
  line L10 (-0.65, 35.6726) -> (-0.65, -0.9975)
  line L11 (-0.65, 43) -> (-0.65, 43)
  line L12 (2.35, 52.4025) -> (2.35, 45)
  line L13 (10.35, 56.4025) -> (6.35, 56.4025)
  line L14 (-0.65, -0.9975) -> (10.35, -0.9975)
  line L15 (21.35, -0.9975) -> (10.35, -0.9975)
  line L16 (21.35, 35.6726) -> (21.35, -0.9975)
  line L17 (18.35, 52.4025) -> (18.35, 45)
  line L18 (10.35, 56.4025) -> (14.35, 56.4025)
  line L19 (23.35, 35.6726) -> (23.35, -2.9975)
  line L20 (23.35, -2.9975) -> (17.85, -2.9975)
  line L21 (-2.65, -2.9975) -> (5.1769, -2.9975)
  line L22 (10.35, 60.8025) -> (10.35, 56.4025)
  line L23 (15.85, -4.9975) -> (10.35, -4.9975)
  line L24 (17.85, -2.9975) -> (15.85, -4.9975)
  line L25 (19.097, -4.9975) -> (15.85, -4.9975)
  line L26 (-2.65, -2.9975) -> (2.85, -2.9975)
  line L27 (2.85, -2.9975) -> (4.85, -4.9975)
  line L28 (4.85, -4.9975) -> (10.35, -4.9975)
  line L29 (17.85, -2.9975) -> (2.85, -2.9975)
  line L30 (-0.58, -0.9275) -> (10.35, -0.9275)
  line L31 (-0.58, 35.6726) -> (-0.58, -0.9275)
  line L32 (2.42, 52.4025) -> (2.42, 45)
  line L33 (10.35, 56.3325) -> (6.35, 56.3325)
  line L34 (10.35, 56.3325) -> (14.35, 56.3325)
  line L35 (18.28, 52.4025) -> (18.28, 45)
  line L36 (21.28, 35.6726) -> (21.28, -0.9275)
  line L37 (21.28, -0.9275) -> (10.35, -0.9275)
  closed curve K4 centre (11, 35.8845)
  closed curve K5 centre (-1.885, 44.5)
  closed curve K6 centre (5.315, 52.7048)
  closed curve K7 centre (15.385, 52.7048)
  closed curve K8 centre (22.585, 44.5)
  closed curve K9 centre (9.7, 35.8845)
  arc A1 centre (-0.65, 45) radius 3 clockwise from (2.35, 45) to (1.7875, 43.2511)
  arc A2 centre (12.35, 35.6726) radius 13 clockwise from (-0.65, 35.6726) to (1.7875, 43.2511)
  arc A3 centre (21.35, 45) radius 3 clockwise from (18.9125, 43.2511) to (18.35, 45)
  arc A4 centre (6.35, 52.4025) radius 4 clockwise from (2.35, 52.4025) to (6.35, 56.4025)
  arc A5 centre (8.35, 35.6726) radius 13 clockwise from (18.9125, 43.2511) to (21.35, 35.6726)
  arc A6 centre (21.35, 45) radius 3 clockwise from (18.9125, 43.2511) to (18.35, 45)
  arc A7 centre (14.35, 52.4025) radius 4 clockwise from (14.35, 56.4025) to (18.35, 52.4025)
  arc A8 centre (19.35, 54.3429) radius 2 clockwise from (20.7827, 55.7384) to (21.35, 54.3429)
  arc A9 centre (12.35, 35.6726) radius 12.93 clockwise from (-0.58, 35.6726) to (1.8444, 43.2103)
  arc A10 centre (-0.65, 45) radius 3.07 clockwise from (2.42, 45) to (1.8444, 43.2103)
  arc A11 centre (6.35, 52.4025) radius 3.93 clockwise from (2.42, 52.4025) to (6.35, 56.3325)
  arc A12 centre (14.35, 52.4025) radius 3.93 clockwise from (14.35, 56.3325) to (18.28, 52.4025)
  arc A13 centre (21.35, 45) radius 3.07 clockwise from (18.8556, 43.2103) to (18.28, 45)
  arc A14 centre (8.35, 35.6726) radius 12.93 clockwise from (18.8556, 43.2103) to (21.28, 35.6726)
  point P8 (5.315, 55.4048)
  point P26 (5.315, 55.4048)
  point P10 (15.385, 55.4048)
  point P27 (15.385, 55.4048)
  point P33 (2.35, 45)
  point P40 (18.35, 45)
  point P36 (1.7875, 43.2511)
  point P38 (18.9125, 43.2511)
  point P28 (10.35, -0.9975)
  point P44 (10.35, -0.9975)
  point P29 (10.35, 56.4025)
  point P53 (10.35, 56.4025)
  point P30 (-0.65, -0.9975)
  point P45 (21.35, -0.9975)
  point P50 (18.35, 45)
  point P35 (-0.65, 35.6726)
  point P46 (21.35, 35.6726)
  point P48 (18.9125, 43.2511)
  point P41 (2.35, 52.4025)
  point P51 (18.35, 52.4025)
  point P42 (6.35, 56.4025)
  point P52 (14.35, 56.4025)
  point P56 (23.35, -2.9975)
  point P71 (-2.65, -2.9975)
  point P66 (10.35, -4.9975)
  point P73 (10.35, -4.9975)
  point P67 (15.85, -4.9975)
  point P72 (4.85, -4.9975)
  point P69 (17.85, -2.9975)
  point P70 (2.85, -2.9975)
  point P5 (2.615, 44.5)
  coincident P8 P26
  coincident P10 P27
  perpendicular L2 L9
  horizontal L11
  tangent L11 A1
  tangent L12 A1
  tangent L10 A2
  tangent A1 A2
  perpendicular L9 L13
  perpendicular L10 L14
  symmetric L9 P33 P40
  symmetric L9 A1 A3
  symmetric L9 P36 P38
  tangent L12 A4
  tangent L13 A4
  symmetric P28 L9 P44
  symmetric P29 L9 P53
  symmetric L9 P30 P45
  symmetric L9 P33 P50
  symmetric L9 A1 A6
  symmetric L9 P35 P46
  symmetric L9 P36 P48
  symmetric L9 A2 A5
  symmetric L9 P41 P51
  symmetric L9 P42 P52
  symmetric L9 A4 A7
  perpendicular L18 L22
  perpendicular L9 L23
  horizontal L25
  symmetric L9 P56 P71
  symmetric L9 P66 P73
  symmetric L9 P67 P72
  symmetric L9 P69 P70
  parallel L20 L29
  dimension "d85" distance P28 P29 = 57.4
  dimension "d92" radius A1 = 3
  dimension "d94" radius A2 = 13
  dimension "d95" distance P28 P30 = 11
  dimension "d96" radius A4 = 4
  dimension "d97" distance P30 P35 = 36.6701
  dimension "d98" distance P30 P36 = 44.2486
  dimension "d99" distance P5 P30 = 45.4975
  dimension "d100" distance P30 P41 = 53.4
  dimension "d111" radius A8 = 2
  dimension "d113" distance P66 P67 = 5.5
  dimension "d114" angle L24 L25 = 45
  dimension "d303" = 0.07
work_plane "WorkPlane1" AlongDistance -60.803
work_plane "WorkPlane2" AlongDistance 8
extrude "Extrude15" cut blind -26
extrude "Extrude18" cut distance 6.19
extrude "Extrude19" new body sketch "mag body proper" profile of L9 L37 L36 A14 A11 L30 A13 L31 A10 L32 L34 A9 L35 A12 L33 along normal blind 3.43
sketch "extruded features z" plane through (0, 3.43, 0) normal (0, 1, 0) x axis (-1, 0, 0)
  line L1 (-21.28, 0.9275) -> (0.58, 0.9275)
  line L2 (-21.28, -35.6726) -> (-21.28, 0.9275)
  line L3 (-18.28, -52.4025) -> (-18.28, -45)
  line L4 (-6.35, -56.3325) -> (-14.35, -56.3325)
  line L5 (-2.42, -45) -> (-2.42, -52.4025)
  line L6 (0.58, 0.9275) -> (0.58, -35.6726)
  line L7 (0.58, 0.9275) -> (-21.28, 0.9275)
  line L8 (-15.45, -21.7725) -> (-10.35, -21.7725)
  line L9 (-5.25, -21.7725) -> (-10.35, -21.7725)
  line L10 (-5.25, -24.7725) -> (-5.25, -21.7725)
  line L11 (-15.45, -24.7725) -> (-5.25, -24.7725)
  line L12 (-15.45, -21.7725) -> (-15.45, -24.7725)
  line L13 (-11.475, -5.2725) -> (-10.35, -5.2725)
  line L14 (-9.225, -5.2725) -> (-10.35, -5.2725)
  line L15 (-11.475, -21.7725) -> (-11.475, -5.2725)
  line L16 (-9.225, -21.7725) -> (-9.225, -5.2725)
  line L17 (-11.475, -41.4725) -> (-11.85, -24.7725)
  line L18 (-11.85, -24.7725) -> (-8.85, -24.7725)
  line L19 (-9.2256, -41.422) -> (-11.475, -41.4725)
  line L20 (-8.85, -24.7725) -> (-9.2256, -41.422)
  arc A1 centre (-8.35, -35.6726) radius 12.93 clockwise from (-18.8556, -43.2103) to (-21.28, -35.6726)
  arc A2 centre (-21.35, -45) radius 3.07 clockwise from (-18.8556, -43.2103) to (-18.28, -45)
  arc A3 centre (-14.35, -52.4025) radius 3.93 clockwise from (-14.35, -56.3325) to (-18.28, -52.4025)
  arc A4 centre (-6.35, -52.4025) radius 3.93 clockwise from (-2.42, -52.4025) to (-6.35, -56.3325)
  arc A5 centre (0.65, -45) radius 3.07 clockwise from (-2.42, -45) to (-1.8444, -43.2103)
  arc A6 centre (-12.35, -35.6726) radius 12.93 clockwise from (0.58, -35.6726) to (-1.8444, -43.2103)
  point P3 (-21.28, 0.9275)
  point P20 (-21.28, 0.9275)
  point P2 (0.58, 0.9275)
  point P21 (0.58, 0.9275)
  point P30 (-11.475, -21.7725)
  point P31 (-9.225, -21.7725)
  point P22 (-10.35, -21.7725)
  point P23 (-15.45, -21.7725)
  point P24 (-5.25, -21.7725)
  point P25 (-5.25, -24.7725)
  point P26 (-15.45, -24.7725)
  point P27 (-10.35, -5.2725)
  point P29 (-9.225, -5.2725)
  point P28 (-11.475, -5.2725)
  point P33 (-11.85, -24.7725)
  point P34 (-8.85, -24.7725)
  point P32 (-11.475, -41.4725)
  point P35 (-9.2256, -41.422)
  coincident P3 P20
  coincident P2 P21
  perpendicular L9 L10
  perpendicular L10 L11
  coincident L8 P30
  perpendicular L8 L15
  coincident L9 P31
  perpendicular L9 L16
  parallel L11 L18
  perpendicular L17 L19
  dimension "d307" distance P22 P23 = 5.1
  dimension "d308" distance P22 P24 = 5.1
  dimension "d309" distance P24 P25 = 3
  dimension "d310" distance P25 P26 = 10.2
  dimension "d313" distance P27 P29 = 1.125
  dimension "d314" distance L8 L13 = 16.5
  dimension "d335" distance P28 P29 = 2.25
  dimension "d339" distance P33 P34 = 3
  dimension "d340" distance P32 P35 = 2.25
extrude "Extrude20" add sketch "extruded features z" profile of L8 L9 L10 L11 L12 along normal blind 2.6
sketch "Sketch25" plane through (0, 6.03, 0) normal (0, 1, 0) x axis (-1, 0, 0)
  line L1 (-15.45, -21.7725) -> (-5.25, -21.7725)
  line L2 (-15.45, -24.7725) -> (-15.45, -21.7725)
  line L3 (-5.25, -24.7725) -> (-15.45, -24.7725)
  line L4 (-5.25, -21.7725) -> (-5.25, -24.7725)
  line L5 (-15.45, -21.7725) -> (-5.25, -21.7725)
  line L6 (-2.85, -21.7725) -> (-17.85, -21.7725)
  line L7 (-2.85, -24.7725) -> (-2.85, -21.7725)
  line L8 (-17.85, -24.7725) -> (-2.85, -24.7725)
  line L9 (-17.85, -21.7725) -> (-17.85, -24.7725)
  point P2 (-5.25, -21.7725)
  point P6 (-5.25, -21.7725)
  point P3 (-15.45, -21.7725)
  point P7 (-15.45, -21.7725)
  point P8 (-17.85, -21.7725)
  point P9 (-2.85, -21.7725)
  point P11 (-17.85, -24.7725)
  coincident P2 P6
  coincident P3 P7
  horizontal L6
  vertical L7
  horizontal L8
  vertical L9
  dimension "d319" distance P8 P9 = 15
  dimension "d320" distance P8 P11 = 3
extrude "Extrude21" add sketch "Sketch25" along normal blind 3
sketch "Sketch26" plane through (0, 9.03, 0) normal (0, 1, 0) x axis (-1, 0, 0)
  line L1 (-2.85, -24.7725) -> (-17.85, -24.7725)
  line L2 (-2.85, -21.7725) -> (-2.85, -24.7725)
  line L3 (-17.85, -21.7725) -> (-2.85, -21.7725)
  line L4 (-17.85, -24.7725) -> (-17.85, -21.7725)
  line L5 (25.5759, -27.2354) -> (28.5759, -27.2354)
  line L6 (25.5759, -24.2354) -> (25.5759, -27.2354)
  line L7 (28.5759, -24.2354) -> (25.5759, -24.2354)
  line L8 (28.5759, -27.2354) -> (28.5759, -24.2354)
  point P6 (28.5759, -27.2354)
  point P7 (25.5759, -27.2354)
  point P9 (28.5759, -24.2354)
  horizontal L5
  vertical L6
  horizontal L7
  vertical L8
  dimension "d323" distance P6 P7 = 3
  dimension "d324" distance P6 P9 = 3
extrude "Extrude22" new body sketch "Sketch26" profile of L1 L2 L3 L4 along normal blind 15
draft "Draft8" Angle1 18.5 Angle2 0
draft "Draft9" Angle1 8.5 Angle2 0
extrude "Extrude23" add of existing geometry blind 8.54
fillet "Fillet31" radius 40
combine "Combine2"
extrude "Extrude26" add sketch "extruded features z" profile of L11 L17 L18 L19 L20 to an object
chamfer "Chamfer6" distance 27 distance 13
fillet "Fillet35" radius 0.5
fillet "Fillet32" radius 1
fillet "Fillet33" radius 0.5
fillet "Fillet36" radius 0.49
fillet "Fillet37" radius 1.5
fillet "Fillet38" radius 0.5
extrude "Extrude27" add sketch "extruded features z" profile of L8 L9 L13 L14 L15 L16 along normal blind 2.6
sketch "Sketch27" plane through (0, 6.03, 0) normal (0, 1, 0) x axis (-1, 0, 0)
  line L1 (-11.475, -5.2725) -> (-9.225, -5.2725)
  line L2 (-11.475, -21.7725) -> (-11.475, -5.2725)
  line L3 (-9.225, -21.7725) -> (-11.475, -21.7725)
  line L4 (-9.225, -5.2725) -> (-9.225, -21.7725)
  line L5 (-9.225, -21.7725) -> (-11.475, -21.7725)
  line L6 (-11.475, -0.7725) -> (-11.475, -21.7725)
  line L7 (-9.225, -0.7725) -> (-9.225, -21.7725)
  line L8 (-11.475, -0.7725) -> (-9.225, -0.7725)
  point P4 (-11.475, -21.7725)
  point P6 (-11.475, -21.7725)
  point P5 (-9.225, -21.7725)
  point P7 (-9.225, -21.7725)
  point P8 (-11.475, -0.7725)
  point P9 (-9.225, -0.7725)
  coincident P4 P6
  coincident P5 P7
  perpendicular L3 L6
  perpendicular L3 L7
  dimension "d365" distance P6 P8 = 21
  dimension "d366" distance P7 P9 = 21
extrude "Extrude28" add sketch "Sketch27" along normal blind 2
draft "Draft10" Angle1 -4 Angle2 0
draft "Draft11" Angle1 4 Angle2 0
extrude "Extrude29" add of existing geometry blind 2 taper 4
extrude "Extrude30" add of existing geometry blind 2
